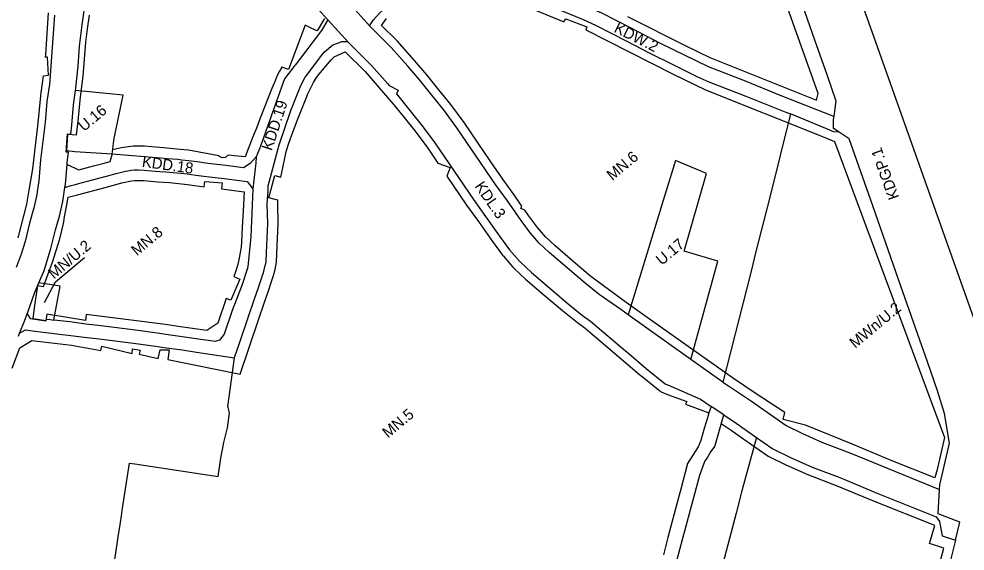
# Model space of a CAD drawing. Extents: x 7418616 to 7420822, y 5550745 to 5553106.
# Drawn here: x 7420139.9 to 7420570.2, y 5551952.8 to 5552194.8 of the extents above; entities that cross this region are included whole.
import ezdxf

# ---------------------------------------------------------------- set-up
doc = ezdxf.new("R2010")
doc.units = 0
for name, color, linetype in [('granica obszaru objętego planem', 7, 'Continuous'), ('linie rozgraniczające', 7, 'Continuous'), ('nieprzekraczalne linie zabudowy', 7, 'Continuous'), ('przeznaczenia terenów', 7, 'Continuous')]:
    doc.layers.add(name, color=color, linetype=linetype)

msp = doc.modelspace()

# ---------------------------------------------------------------- linework, layer by layer
at = {"layer": 'granica obszaru objętego planem'}
msp.add_lwpolyline([(7420419.04, 5552462.29), (7420427.01, 5552448.46), (7420437.26, 5552429.47), (7420442.19, 5552419.71), (7420448.72, 5552405.7), (7420457.17, 5552386.45), (7420461.96, 5552374), (7420467.81, 5552358.36), (7420579.74, 5552042.73), (7420611.64, 5551954.27), (7420788.95, 5551466.82)], dxfattribs=at)
at = {"layer": 'linie rozgraniczające'}
for p, q in [((7420290.31, 5552201.68), (7420299.38, 5552191.7)), ((7420289.78, 5552184.13), (7420280.43, 5552194.41))]:
    msp.add_line(p, q, dxfattribs=at)
for points in [[(7420419.04, 5552462.29), (7420427.01, 5552448.46), (7420437.26, 5552429.47), (7420442.19, 5552419.71), (7420448.72, 5552405.7), (7420457.17, 5552386.45), (7420461.96, 5552374), (7420467.81, 5552358.36), (7420579.74, 5552042.73), (7420611.64, 5551954.27), (7420788.95, 5551466.82)], [(7420448.7, 5552336.96), (7420451.94, 5552327.62), (7420461.42, 5552300.34), (7420463.82, 5552293.51), (7420474.63, 5552262.64), (7420476.31, 5552257.86), (7420480.62, 5552245.56), (7420486.65, 5552228.38), (7420501.73, 5552185.39), (7420507.3, 5552169.51), (7420511.47, 5552157.62), (7420510.58, 5552150.44)], [(7420165.63, 5552162.35), (7420165.79, 5552163.56), (7420166.88, 5552173.32), (7420167.39, 5552182.4), (7420168.63, 5552192.12), (7420170.71, 5552207.15), (7420172.35, 5552214.02), (7420174.2, 5552222.27), (7420176.1, 5552228.5), (7420177.86, 5552235.65), (7420180.13, 5552242.24), (7420182.98, 5552250.89), (7420186.53, 5552261.31), (7420185.48, 5552262.3), (7420188.25, 5552270.3), (7420189.45, 5552269.64), (7420191.78, 5552275.82), (7420194.01, 5552282.71), (7420196.22, 5552285.43)], [(7420196.22, 5552285.43), (7420199.55, 5552287.03), (7420200.16, 5552286.99), (7420200.22, 5552286.94), (7420200.25, 5552286.99), (7420203.3, 5552286.79), (7420207.25, 5552284.61), (7420215.17, 5552276.75), (7420214.4, 5552275.92), (7420214.17, 5552273.43), (7420221.62, 5552265.21), (7420231.62, 5552252.98), (7420238.08, 5552245.19), (7420240.15, 5552242.14), (7420254.47, 5552225.38), (7420255.89, 5552223.73), (7420265.53, 5552212.15), (7420266.93, 5552209.16), (7420271.11, 5552205.29), (7420275.99, 5552199.28), (7420280.43, 5552194.41)], [(7420299.38, 5552191.7), (7420301.18, 5552194.46), (7420303.69, 5552197.26), (7420309.64, 5552202.83), (7420316.37, 5552209.46), (7420319.68, 5552212.62), (7420322.42, 5552214.39), (7420326.54, 5552219.79)], [(7420326.54, 5552219.79), (7420330.88, 5552220.61), (7420334.57, 5552219.2), (7420343.23, 5552216.21), (7420352.73, 5552212.89), (7420362.54, 5552209.07), (7420367.26, 5552206.9), (7420379.81, 5552201.42), (7420396.44, 5552194.54), (7420402.05, 5552191.99), (7420416.32, 5552184.66), (7420426.58, 5552179.37), (7420437.35, 5552174.15), (7420448.25, 5552168.67), (7420453.73, 5552166.18), (7420470.56, 5552159.75), (7420488.72, 5552152.48), (7420490.75, 5552151.65)], [(7420510.58, 5552150.44), (7420486.58, 5552159.81), (7420470.3, 5552166.54), (7420453.57, 5552173.11), (7420431.71, 5552183.65), (7420418.04, 5552190.76), (7420405.05, 5552197.48), (7420401.2, 5552199.16)], [(7420156.02, 5552196.51), (7420153.71, 5552165), (7420152.62, 5552157.32), (7420151.76, 5552147.73), (7420149.74, 5552130.72), (7420148.88, 5552121.24), (7420147.82, 5552114.16), (7420146.64, 5552108.9), (7420144.71, 5552101.91), (7420142.63, 5552093.6), (7420140.84, 5552087.78), (7420138.63, 5552081.71)], [(7420280.43, 5552194.41), (7420277.45, 5552189.56), (7420265.46, 5552173.81), (7420265.23, 5552173.46), (7420260.66, 5552167.57), (7420255.55, 5552153.25), (7420251.11, 5552140.79), (7420249.32, 5552135.76), (7420247.78, 5552132.15)], [(7420417, 5552060.28), (7420413.69, 5552062.64), (7420403.78, 5552069.57), (7420397.44, 5552074.68), (7420389.19, 5552081.66), (7420381.08, 5552088.61), (7420376.5, 5552092.92), (7420372.56, 5552097.4), (7420368.36, 5552103.09), (7420362.07, 5552112.13), (7420356.64, 5552119.6), (7420339.07, 5552145.36), (7420333, 5552153.67), (7420327.72, 5552160.15), (7420322.21, 5552167.05), (7420316.79, 5552173.36), (7420309.23, 5552181.9), (7420299.77, 5552191.28), (7420299.38, 5552191.7)], [(7420237.91, 5552040.62), (7420237.95, 5552040.75), (7420237.95, 5552040.88), (7420240.2, 5552047.36), (7420244.34, 5552059.51), (7420246.93, 5552067.04), (7420248.85, 5552072.69), (7420250.23, 5552076.83), (7420250.71, 5552078.34), (7420251.07, 5552079.41), (7420251.74, 5552082.03), (7420252.12, 5552083.6), (7420252.32, 5552084.69), (7420252.59, 5552092.1), (7420252.81, 5552095.1), (7420253.01, 5552101.85), (7420252.83, 5552110.65), (7420253.06, 5552114.93), (7420253.18, 5552116.6), (7420253.3, 5552118.88), (7420258.27, 5552137.5), (7420263.59, 5552153.12), (7420268.07, 5552164.51), (7420270.07, 5552168.3), (7420270.85, 5552169.31), (7420271.18, 5552169.77), (7420278.13, 5552178.94), (7420278.82, 5552179.8), (7420282.62, 5552183.01), (7420286.91, 5552184.56), (7420288.91, 5552184.5), (7420289.6, 5552184.33)], [(7420289.78, 5552184.13), (7420291.06, 5552182.73), (7420300.23, 5552173.66), (7420307.6, 5552165.33), (7420308.25, 5552164.57), (7420312.32, 5552162.41), (7420311.53, 5552160.76), (7420312.88, 5552159.18), (7420318.24, 5552152.46), (7420323.33, 5552146.22), (7420329.05, 5552138.41), (7420346.61, 5552112.64), (7420352.16, 5552105.01), (7420358.39, 5552096.05), (7420362.97, 5552089.85), (7420367.53, 5552084.64), (7420367.8, 5552084.36), (7420372.98, 5552079.48), (7420381.28, 5552072.38), (7420389.72, 5552065.22), (7420396.28, 5552059.94), (7420399.9, 5552057.39), (7420413.98, 5552045.39), (7420417.39, 5552042.48), (7420425.18, 5552035.83), (7420433.83, 5552028.86), (7420436.38, 5552027.76), (7420449.88, 5552021.9), (7420454.77, 5552018.54)], [(7420161.8, 5552128.62), (7420161.88, 5552129.53), (7420162.44, 5552134.27), (7420161.39, 5552134.28), (7420161.9, 5552142.55), (7420163.42, 5552142.46), (7420163.9, 5552146.55), (7420164.73, 5552155.83), (7420165.63, 5552162.35)], [(7420182.32, 5552133.29), (7420183.26, 5552140.62), (7420183.5, 5552142.02), (7420187.26, 5552160.13), (7420181.05, 5552160.78), (7420165.63, 5552162.35)], [(7420490.75, 5552151.65), (7420486.06, 5552132.73), (7420481.23, 5552113.22), (7420475.11, 5552089.07), (7420472.85, 5552080.15), (7420460.08, 5552029.69)], [(7420512.93, 5552143.32), (7420510.57, 5552143.56), (7420490.75, 5552151.65)], [(7420512.93, 5552143.32), (7420510.42, 5552144.98), (7420510.34, 5552148.47), (7420510.58, 5552150.44)], [(7420558.64, 5551980.88), (7420558.74, 5551982.86), (7420563.18, 5552001.94), (7420560.86, 5552015.44), (7420557.75, 5552025.7), (7420553.12, 5552038.91), (7420548.77, 5552051.28), (7420540, 5552076.28), (7420528.22, 5552109.89), (7420519.2, 5552135.59), (7420517.56, 5552140.25), (7420512.93, 5552143.32)], [(7420161.8, 5552128.62), (7420167.12, 5552126.16), (7420173.74, 5552127.96), (7420177.96, 5552129.08), (7420181.41, 5552130.03), (7420182.31, 5552133.19), (7420182.32, 5552133.29)], [(7420217.09, 5552130.29), (7420214.02, 5552130.65), (7420212.2, 5552130.83), (7420207.23, 5552131.28), (7420204.43, 5552131.47), (7420198.7, 5552131.95), (7420197.21, 5552132.09), (7420182.32, 5552133.29)], [(7420160.77, 5552118.22), (7420160.99, 5552119.61), (7420161.8, 5552128.62)], [(7420247.78, 5552132.15), (7420245.05, 5552129.05), (7420241.97, 5552127.15), (7420233.95, 5552128.19), (7420231.22, 5552128.5), (7420227.18, 5552129), (7420224.7, 5552129.29), (7420221.93, 5552129.67), (7420217.09, 5552130.29)], [(7420247.78, 5552132.15), (7420247.67, 5552129.34), (7420246.24, 5552117.58)], [(7420445.55, 5552039.95), (7420457.69, 5552084.66), (7420442.47, 5552089.15), (7420452.61, 5552124.54), (7420438.53, 5552130.52), (7420432.96, 5552112.33), (7420417, 5552060.28)], [(7420160.77, 5552118.22), (7420163.7, 5552119.05), (7420165.02, 5552119.38), (7420166.55, 5552119.79), (7420175.58, 5552122.24), (7420179.72, 5552123.34), (7420184.17, 5552124.57), (7420185.99, 5552125.04), (7420187.19, 5552125.27), (7420188.3, 5552125.53), (7420189.34, 5552125.75), (7420190.22, 5552125.91), (7420191.05, 5552126.03), (7420192.24, 5552126.17), (7420194.32, 5552126.2), (7420196.81, 5552126.1), (7420198.18, 5552125.97), (7420203.98, 5552125.49), (7420206.75, 5552125.3), (7420211.64, 5552124.86), (7420213.36, 5552124.68), (7420216.36, 5552124.33), (7420220.37, 5552123.83), (7420223.96, 5552123.33), (7420226.48, 5552123.05), (7420230.5, 5552122.55), (7420233.22, 5552122.23), (7420239.02, 5552121.49), (7420243.7, 5552120.86), (7420246.24, 5552117.58)], [(7420148.96, 5552074.79), (7420151.31, 5552080.44), (7420151.45, 5552080.81), (7420154.43, 5552090.48), (7420156.53, 5552098.88), (7420158.27, 5552105.2), (7420159.79, 5552111.83), (7420160.77, 5552118.22)], [(7420246.24, 5552117.58), (7420245.38, 5552095.77), (7420244.03, 5552082.18), (7420243.87, 5552081.5), (7420241.25, 5552073.64), (7420236.92, 5552062.19), (7420233.21, 5552051.4), (7420231.15, 5552048.69), (7420229.1, 5552048.07), (7420221.54, 5552049.25), (7420206.65, 5552051.37), (7420203.81, 5552051.81), (7420196.2, 5552052.79), (7420192.86, 5552053.27), (7420177.14, 5552055.29), (7420170.3, 5552056.07), (7420162.96, 5552057.01), (7420155.72, 5552057.87)], [(7420143.67, 5552060.78), (7420143.93, 5552061.45), (7420147.01, 5552070.08), (7420148.96, 5552074.79)], [(7420155.72, 5552057.87), (7420158.68, 5552073.32), (7420148.96, 5552074.79)], [(7420140.16, 5552051.86), (7420142.36, 5552057.4), (7420143.67, 5552060.78)], [(7420143.67, 5552060.78), (7420144.92, 5552058.61), (7420152.24, 5552057.46), (7420152.36, 5552058.3), (7420154.14, 5552058.09), (7420155.72, 5552057.87)], [(7420445.55, 5552039.95), (7420423.33, 5552055.75), (7420417, 5552060.28)], [(7420139.65, 5552050.57), (7420140.16, 5552051.86)], [(7420140.16, 5552051.86), (7420142.87, 5552053.46), (7420146.02, 5552053.04), (7420146.04, 5552053), (7420153.38, 5552052.13), (7420154.78, 5552051.94), (7420158.24, 5552051.52), (7420162.23, 5552051.06), (7420169.58, 5552050.11), (7420176.42, 5552049.33), (7420192.05, 5552047.33), (7420195.38, 5552046.84), (7420202.98, 5552045.86), (7420205.78, 5552045.44), (7420214.1, 5552044.26), (7420220.65, 5552043.31), (7420237.91, 5552040.62)], [(7420193.57, 5551873.49), (7420195.82, 5551883.31), (7420198.98, 5551898.48), (7420202.06, 5551910.66), (7420204.15, 5551920.87), (7420179.92, 5551925.55), (7420183.78, 5551950.94), (7420185.03, 5551959.25), (7420186.02, 5551965.86), (7420186.46, 5551968.78), (7420187.03, 5551972.47), (7420187.29, 5551974.18), (7420188.03, 5551979.07), (7420190.09, 5551992.79), (7420192.66, 5551992.53), (7420230.5, 5551986.79), (7420231.69, 5551995.09), (7420233, 5552002.11), (7420234.81, 5552008.88), (7420235.65, 5552015.65), (7420235.1, 5552018.04), (7420234.95, 5552018.56), (7420235.55, 5552023.03), (7420237.91, 5552040.62)], [(7420460.08, 5552029.69), (7420454.82, 5552033.31), (7420445.55, 5552039.95)], [(7420460.08, 5552029.69), (7420462.57, 5552027.98), (7420473.02, 5552020.98), (7420488.88, 5552009.89), (7420495.9, 5552006.43), (7420505.32, 5552002.24), (7420517.77, 5551997.54), (7420535.16, 5551990.3), (7420558.64, 5551980.88)], [(7420454.77, 5552018.54), (7420453.67, 5552015.69), (7420453.01, 5552013.41), (7420451.47, 5552008.59), (7420449.97, 5552003.09), (7420448.78, 5552000.23), (7420444, 5551992.68), (7420440.86, 5551980.91), (7420439.7, 5551976.57), (7420435.02, 5551959.02), (7420432.98, 5551951.04)], [(7420460.44, 5552014.75), (7420455.69, 5552017.91), (7420454.77, 5552018.54)], [(7420437.88, 5551943.99), (7420444.41, 5551968.18), (7420449.54, 5551987.29), (7420451.04, 5551991.61), (7420451.85, 5551993.5), (7420452.97, 5551995.08), (7420454.34, 5551997.47), (7420456.41, 5552000.31), (7420460.44, 5552014.75)], [(7420460.44, 5552014.75), (7420466.07, 5552010.95), (7420475.4, 5552004.42)], [(7420475.4, 5552004.42), (7420468.68, 5551980.21), (7420466.09, 5551970.04), (7420455.5, 5551929.73), (7420444.96, 5551889.52), (7420439.84, 5551873.32), (7420431, 5551838.75), (7420420.77, 5551795.07)], [(7420475.4, 5552004.42), (7420482.38, 5551999.55), (7420482.72, 5551999.34), (7420490.83, 5551995.33), (7420500.66, 5551990.96), (7420513.18, 5551986.23), (7420530.52, 5551979.02), (7420557.08, 5551968.36), (7420558.65, 5551966.24), (7420559.87, 5551959.78), (7420565.81, 5551957.74)], [(7420565.81, 5551957.74), (7420567.85, 5551966.01), (7420558, 5551969.7), (7420558.63, 5551980.76), (7420558.64, 5551980.88)], [(7420565.81, 5551957.74), (7420562.67, 5551944.97), (7420570.65, 5551934.55), (7420586.79, 5551913.47), (7420595.95, 5551901.87)]]:
    msp.add_lwpolyline(points, dxfattribs=at)
at = {"layer": 'nieprzekraczalne linie zabudowy'}
for points in [[(7420416.71, 5552195.95), (7420443.24, 5552182.54), (7420454.06, 5552177.31), (7420502.7, 5552157.92), (7420503.34, 5552160.95), (7420479.66, 5552227.74)], [(7420365.33, 5552202.71), (7420387.71, 5552193.54), (7420388.63, 5552194.94), (7420398.14, 5552191.25), (7420397.69, 5552189.86), (7420437.37, 5552169.66), (7420452.12, 5552162.52), (7420505.38, 5552141.33), (7420510.76, 5552139.07), (7420560.93, 5552004.39), (7420557.49, 5551989.86), (7420556.41, 5551986.09), (7420536.67, 5551994.01), (7420519.24, 5552001.26), (7420497.59, 5552010.05), (7420487.51, 5552012.65), (7420488.31, 5552015.85), (7420475.27, 5552024.28), (7420464.82, 5552031.29), (7420450.42, 5552041.38), (7420425.65, 5552059.01), (7420416.03, 5552065.88), (7420399.99, 5552077.76), (7420391.78, 5552084.71), (7420383.76, 5552091.59), (7420379.38, 5552095.7), (7420375.67, 5552099.91), (7420371.61, 5552105.42), (7420369.95, 5552107.81), (7420368.19, 5552108.67), (7420368.66, 5552109.67), (7420365.43, 5552114.31), (7420359.91, 5552121.9), (7420354.51, 5552129.8), (7420342.34, 5552147.67), (7420336.31, 5552155.92), (7420330.83, 5552162.66), (7420325.44, 5552169.42), (7420319.82, 5552175.97), (7420311.89, 5552184.91), (7420304.81, 5552191.91)], [(7420139.59, 5552095.33), (7420143.45, 5552110.54), (7420144.58, 5552117.02), (7420146.12, 5552126.67), (7420147.63, 5552138.52), (7420148.32, 5552144.87), (7420148.9, 5552150.39), (7420149.51, 5552156.85), (7420150.05, 5552161.23), (7420151.03, 5552168.94), (7420153.26, 5552169.29), (7420152.9, 5552177.49), (7420152.01, 5552177.42), (7420152.15, 5552178.72), (7420153.39, 5552197.55)], [(7420182.31, 5552133.29), (7420165.22, 5552134.41), (7420161.67, 5552134.78), (7420162.04, 5552142.46), (7420166.06, 5552142.06), (7420166.82, 5552148.39), (7420167.93, 5552159.33), (7420169.03, 5552168.84), (7420170.34, 5552184.34), (7420171.05, 5552190.34), (7420171.98, 5552196.61)], [(7420278.84, 5552195), (7420275.54, 5552189.35), (7420273.11, 5552190.51), (7420270.1, 5552192.03), (7420262.53, 5552171.77), (7420259.39, 5552172.97), (7420258.39, 5552171.12), (7420257.4, 5552169.06), (7420256.35, 5552166.68), (7420254.93, 5552163.24), (7420249.65, 5552149.75), (7420247.85, 5552145.23), (7420246.62, 5552141.96), (7420244.46, 5552136.55), (7420242.81, 5552132.1), (7420237.8, 5552132.56), (7420235.49, 5552132.86), (7420234.78, 5552132.78), (7420233.78, 5552131.77), (7420232.37, 5552131.59), (7420231.06, 5552132.25), (7420230.81, 5552132.63), (7420216.94, 5552135.08), (7420213.18, 5552135.47), (7420205.62, 5552136.15), (7420200.18, 5552136.61), (7420197, 5552136.9), (7420194.73, 5552136.98), (7420191.84, 5552136.92), (7420188.64, 5552136.57), (7420186.44, 5552136.19), (7420183.83, 5552135.58), (7420182.57, 5552135.26)], [(7420304.81, 5552191.91), (7420307.02, 5552195.01)], [(7420136.74, 5552036.02), (7420140.23, 5552045.22), (7420145.76, 5552048.55), (7420163.79, 5552046.43), (7420177.12, 5552044.05), (7420177.61, 5552045.98), (7420191.3, 5552042.62), (7420191.53, 5552044.86), (7420195.04, 5552044.11), (7420194.61, 5552042.34), (7420203.19, 5552040.37), (7420204.08, 5552044.34), (7420208.17, 5552044.26), (7420207.58, 5552039.87), (7420240.45, 5552033.31), (7420248.83, 5552057.97), (7420251.43, 5552065.51), (7420253.36, 5552071.19), (7420254.78, 5552075.47), (7420255.21, 5552076.83), (7420255.63, 5552078.07), (7420256.36, 5552080.91), (7420256.77, 5552082.61), (7420257.05, 5552084.17), (7420257.33, 5552091.84), (7420257.55, 5552094.86), (7420257.76, 5552101.83), (7420257.58, 5552110.56), (7420257.68, 5552112.37), (7420253.47, 5552113.47), (7420256.21, 5552123.63), (7420258.93, 5552122.88), (7420259.87, 5552127.1), (7420260.91, 5552132.32), (7420261.6, 5552134.97), (7420262.53, 5552137.89), (7420263.4, 5552140.46), (7420264.27, 5552142.81), (7420266.34, 5552148.22), (7420270.88, 5552159.62), (7420271.18, 5552160.45), (7420272.19, 5552162.62), (7420272.61, 5552163.57), (7420273.88, 5552165.92), (7420275.26, 5552168.2), (7420276.28, 5552169.63), (7420277.93, 5552171.52), (7420281.93, 5552176.2), (7420283.32, 5552177.56), (7420288.22, 5552179.91), (7420297.32, 5552170.91), (7420311.18, 5552154.9), (7420315.08, 5552150), (7420320.16, 5552143.78), (7420325.78, 5552136.1), (7420330.41, 5552129.3), (7420335.97, 5552127.33), (7420334.52, 5552123.27), (7420343.48, 5552110.14), (7420348.9, 5552102.69), (7420355.27, 5552093.54), (7420359.87, 5552087.32), (7420360.21, 5552086.91), (7420364.53, 5552082), (7420365.19, 5552081.31), (7420370.29, 5552076.52), (7420378.67, 5552069.34), (7420387.06, 5552062.23), (7420393.92, 5552056.7), (7420397.45, 5552054.23), (7420422.14, 5552033.16), (7420423.31, 5552032.2), (7420431.32, 5552025.75), (7420431.61, 5552025.53), (7420432.06, 5552025.27), (7420434.85, 5552024.06), (7420443.69, 5552020.8), (7420443.12, 5552019.66), (7420453.68, 5552015.72)], [(7420146.28, 5552058.39), (7420147, 5552063.49), (7420148.54, 5552073.57), (7420150.98, 5552073.2), (7420155.12, 5552084.15), (7420158.43, 5552094.78), (7420160.21, 5552101.83), (7420160.34, 5552102.52), (7420160.65, 5552104.87), (7420160.76, 5552105.51), (7420161.23, 5552107.85), (7420162.17, 5552112.85), (7420162.32, 5552113.77), (7420166.47, 5552114.8), (7420179.13, 5552118.23), (7420186.74, 5552120.32), (7420191.13, 5552121.21), (7420192.38, 5552121.4), (7420194.07, 5552121.42), (7420196.86, 5552121.3), (7420202.84, 5552120.81), (7420208.39, 5552120.43), (7420216.5, 5552119.54), (7420224.16, 5552118.49), (7420224.39, 5552120.94), (7420232.31, 5552120.24), (7420232.06, 5552117.51), (7420242.27, 5552116.21), (7420241.82, 5552107.57), (7420241.37, 5552100.07), (7420241.06, 5552093.3), (7420240.89, 5552090.98), (7420240.53, 5552088.63), (7420239.9, 5552085.25), (7420239.22, 5552082.65), (7420238.32, 5552079.86), (7420237.58, 5552077.66), (7420240.33, 5552076.55), (7420236.26, 5552066.97), (7420234.18, 5552067.66), (7420230.32, 5552056.46), (7420225.32, 5552053.07), (7420212.34, 5552054.94), (7420206.59, 5552055.81), (7420170.49, 5552060.47), (7420170.13, 5552057.73), (7420152.63, 5552060.57), (7420152.09, 5552057.48), (7420146.28, 5552058.39)], [(7420558.22, 5551945.61), (7420560.49, 5551954.08), (7420554.04, 5551956.29), (7420556.44, 5551964.43), (7420529.09, 5551975.28), (7420511.71, 5551982.51), (7420499.13, 5551987.27), (7420488.91, 5551991.81), (7420481.18, 5551995.63), (7420480.72, 5551995.88), (7420480.12, 5551996.25), (7420469.6, 5552003.59), (7420463.81, 5552007.65), (7420459.3, 5552010.67)]]:
    msp.add_lwpolyline(points, dxfattribs=at)
at = {"layer": 'przeznaczenia terenów'}
msp.add_lwpolyline([(7420151.56, 5552065.79), (7420156.57, 5552075.32), (7420169.72, 5552086.39)], dxfattribs=at)

# ---------------------------------------------------------------- texts
for s, rotation, p in [('KDW.2', 333.499, (7420410.17, 5552189.06)), ('U.16', 39.8439, (7420169.44, 5552143.38)), ('KDD.19', 71.8242, (7420254.86, 5552134.57)), ('MN.6', 39.8439, (7420409.78, 5552121.06)), ('KDGP.1', 109.8026, (7420540.32, 5552113.7)), ('KDD.18', 352.0477, (7420195.63, 5552127.64)), ('KDL.3', 304.6, (7420346.99, 5552118.75)), ('MN.8', 39.8439, (7420193.52, 5552086.85)), ('MN/U.2', 40.1, (7420155.77, 5552076.28)), ('U.17', 39.8439, (7420432.21, 5552082.51)), ('MWn/U.2', 39.8439, (7420520.24, 5552044.75)), ('MN.5', 39.8439, (7420307.72, 5552003.95))]:
    msp.add_text(s, height=5, rotation=rotation, dxfattribs=at).set_placement(p)

doc.saveas('drawing.dxf')
